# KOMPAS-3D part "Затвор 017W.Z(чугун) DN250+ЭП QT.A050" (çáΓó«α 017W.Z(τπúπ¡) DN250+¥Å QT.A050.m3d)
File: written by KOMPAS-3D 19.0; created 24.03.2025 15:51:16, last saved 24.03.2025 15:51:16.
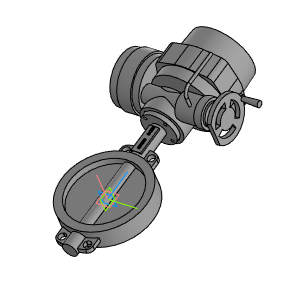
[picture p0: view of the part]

Document properties: Полное имя файла: Затвор 017W.Z(чугун) DN250+ЭП QT.A050.a3d

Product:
- Part/product: Затвор 017W.Z(чугун) DN250+ЭП QT.A050
    Масса: 140.103

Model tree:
1. Операция без истории:1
